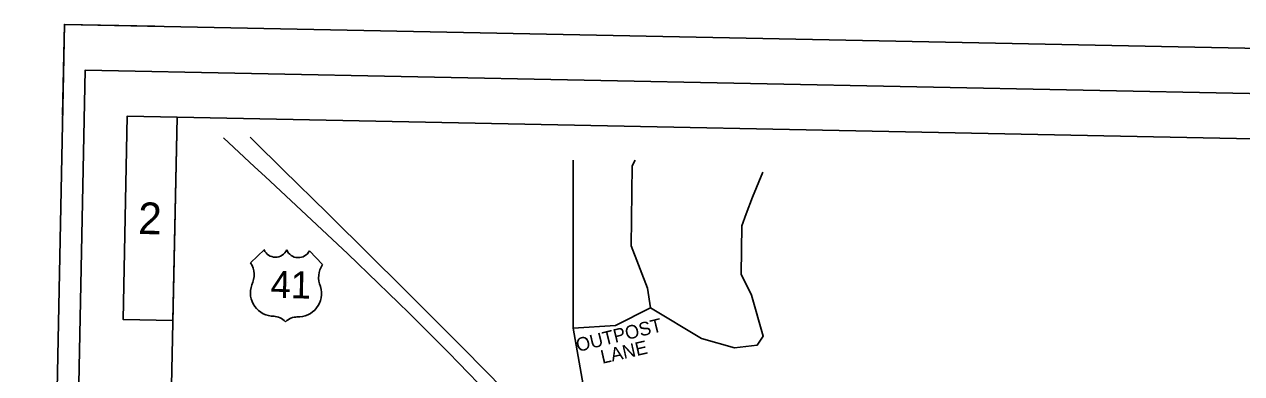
# Model space of a CAD drawing. Extents: x 331323 to 388339, y 121519 to 205315.
# Drawn here: x 354376 to 361104, y 135654 to 137585 of the extents above; entities that cross this region are included whole.
import ezdxf

# ---------------------------------------------------------------- set-up
doc = ezdxf.new("R2010")
doc.units = 0
for name, color, linetype in [('CA-TEXT', 7, 'Continuous'), ('Level 2', 7, 'Continuous'), ('Level 4', 7, 'Continuous'), ('P_RDWY_Text', 7, 'Continuous'), ('PLT_Sheet_Border', 7, 'Continuous'), ('PLT_Sheet_Info', 7, 'Continuous')]:
    doc.layers.add(name, color=color, linetype=linetype)

msp = doc.modelspace()

# ---------------------------------------------------------------- linework, layer by layer
at = {"layer": 'CA-TEXT'}
for p, q in [((355703.1, 136340), (355626.9, 136267.1)), ((355951.4, 136333.7), (356024.5, 136257.4)), ((355828.3, 136159.9), (355828.3, 136159.9))]:
    msp.add_line(p, q, dxfattribs=at)
for centre, radius, start, end in [((355764, 136366.6), 68.5, 203.69631, 335.64775), ((355890, 136363.9), 68.5, 201.88621, 333.83764), ((355517.1, 136199.9), 128.7, 334.57128, 31.45331), ((356131.3, 136185.6), 128.7, 146.08064, 202.96268), ((355754.3, 136100.5), 128.7, 159.86174, 270.95744), ((355890.1, 136096.4), 128.7, 266.57652, 17.67221), ((355749.8, 135877.4), 94.4, 42.5398, 87.52373), ((355885, 135873.4), 94.4, 90.01023, 134.04402)]:
    msp.add_arc(centre, radius, start, end, dxfattribs=at)
at = {"layer": 'Level 2'}
for points in [[(360974.7, 130246.3), (359488.5, 132249.8), (358879.2, 133079.6), (357889.3, 134411.1), (357444.5, 134981.1), (357256, 135199.5), (355476.6, 136957.3)], [(355623.7, 136961.1), (356920.4, 135674.4), (357158.4, 135427.5), (357273.3, 135300.2), (357385.4, 135170.3), (357696.2, 134781.1), (358305.3, 133973.7), (358998.6, 133039.4), (360249.6, 131353.3), (361069.7, 130244.3)]]:
    msp.add_spline(points, degree=3, dxfattribs=at)
at = {"layer": 'Level 4'}
for points in [[(357408.8, 136834.5), (357409.6, 135905.1)], [(357836, 136017.9), (357820.3, 136126.4), (357730.7, 136360.5), (357734.8, 136802.2), (357751.1, 136834)], [(357836, 136017.9), (358118, 135848.7), (358301, 135797), (358426.2, 135812.5), (358460, 135862.2), (358395.4, 136087.8), (358338.1, 136205), (358340.6, 136471.7), (358366.2, 136538.1), (358400.4, 136629.5), (358457.2, 136767.7)], [(357409.6, 135905.1), (357643.3, 135919.6), (357836, 136017.9)], [(357409.6, 135905.1), (357520.6, 135279.1), (357636.8, 135219.7)]]:
    msp.add_lwpolyline(points, dxfattribs=at)
at = {"layer": 'P_RDWY_Text'}
msp.add_lwpolyline([(354597.6, 137585.1), (371594.2, 137242.8), (371372.7, 126245), (354376.1, 126587.3)], close=True, dxfattribs=at)
at = {"layer": 'PLT_Sheet_Border'}
for points in [[(354376.1, 126587.3), (371372.7, 126245), (371594.2, 137242.8), (354597.6, 137585.1)], [(354501.1, 126834.8), (371047.8, 126501.6), (371259.2, 136999.5), (354712.6, 137332.7)]]:
    msp.add_lwpolyline(points, close=True, dxfattribs=at)
at = {"layer": 'PLT_Sheet_Info'}
for p, q in [((354587.6, 137085.2), (354597.6, 137585.1)), ((354597.6, 137585.1), (355097.5, 137575)), ((355018.6, 127074.5), (355219.9, 137072.4)), ((355219.9, 137072.4), (370966.7, 136755.3))]:
    msp.add_line(p, q, dxfattribs=at)
msp.add_lwpolyline([(355219.9, 137072.4), (354945, 137078), (354922.3, 135953.2), (355197.3, 135947.7)], close=True, dxfattribs=at)

# ---------------------------------------------------------------- texts
at = {"layer": 'CA-TEXT'}
for s, height, rotation, p in [('41', 150, 358.76698, (355735.5, 136073.7)), ('OUTPOST', 75, 13.78464, (357435.2, 135773.8)), ('LANE', 75, 12.76146, (357570.5, 135708.4))]:
    msp.add_text(s, height=height, rotation=rotation, dxfattribs=at).set_placement(p)
at = {"layer": 'PLT_Sheet_Info'}
msp.add_text('2', height=175, rotation=358.84622, dxfattribs=at).set_placement((355003.9, 136426.6))

doc.saveas('drawing.dxf')
